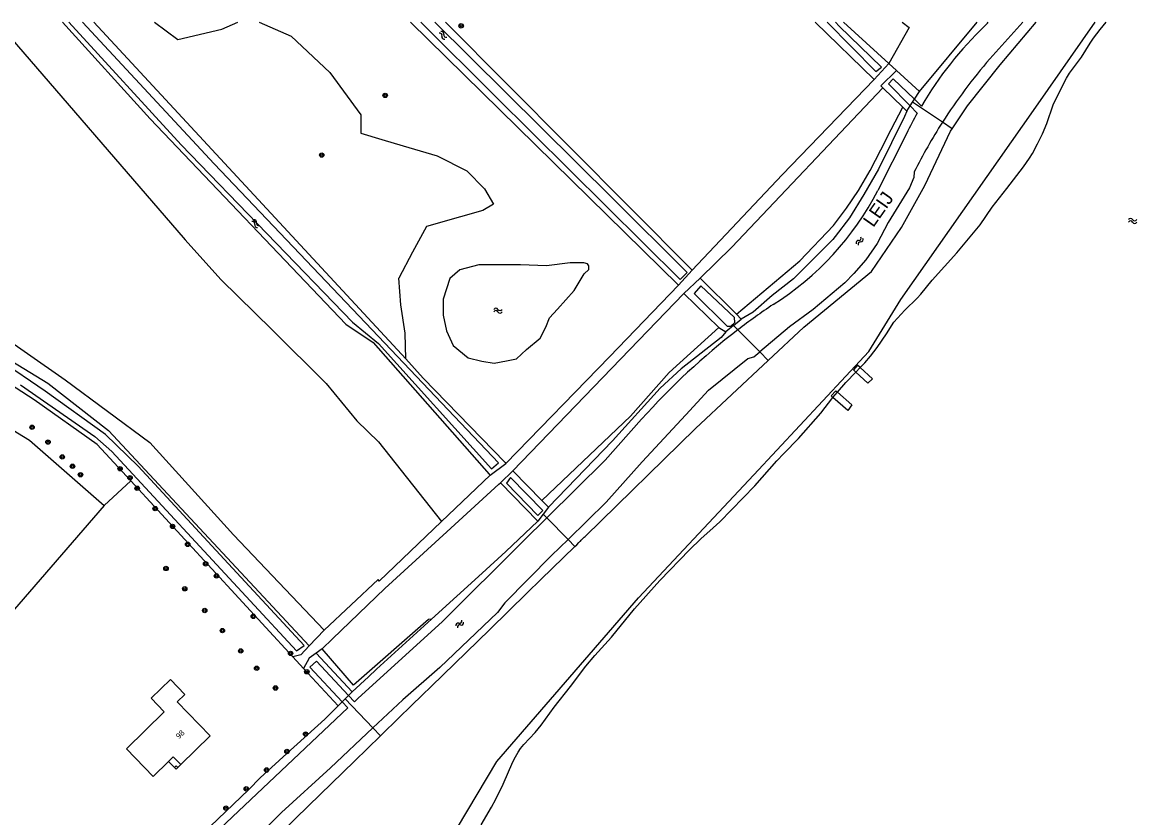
# Model space of a CAD drawing. Extents: x 135990 to 139000, y 393500 to 396000.
# Drawn here: x 136274.9 to 136477.6, y 395855.3 to 396000 of the extents above; entities that cross this region are included whole.
import ezdxf

# ---------------------------------------------------------------- set-up
doc = ezdxf.new("R2010")
doc.units = 0
for name, color, linetype in [('gg-afsc-draadraster', 7, 'Continuous'), ('gg-anno-huisnummerreeks BGT', 7, 'Continuous'), ('gg-anno-naam water', 7, 'Continuous'), ('gg-bbg-hoofdgebouw', 7, 'Continuous'), ('gg-bbg-onder overbouw', 7, 'Continuous'), ('gg-bbg-pand overbouw', 7, 'Continuous'), ('gg-bbg-pilaar onder overbouw', 7, 'Continuous'), ('gg-bbg-pilaar pand', 7, 'Continuous'), ('gg-knt-bronhoudergrens', 7, 'Continuous'), ('gg-kntw-bovenkant insteek waterloop', 7, 'Continuous'), ('gg-kntw-waterlijn', 7, 'Continuous'), ('gg-kwrk-steiger', 7, 'Continuous'), ('gt-grn-groengrens', 7, 'Continuous'), ('gt-grn-vlakafsluiter', 7, 'Continuous'), ('gt-symb-boom', 7, 'Continuous'), ('gt-symb-watersymbool', 7, 'Continuous'), ('gx-grn-maaiveld', 7, 'Continuous')]:
    doc.layers.add(name, color=color, linetype=linetype)

# ---------------------------------------------------------------- blocks, each defined once
blk = doc.blocks.new('gt0-WA')
at = {"layer": 'gt-symb-watersymbool'}
for centre, start, end in [((-0.32, 0.02), 28.0725, 151.9275), ((0.43, 0.42), 208.0725, 331.9275), ((-0.32, -0.43), 28.0725, 151.9275), ((0.43, -0.03), 208.0725, 331.9275)]:
    blk.add_arc(centre, 0.425, start, end, dxfattribs=at)
blk = doc.blocks.new('gt0-BOOM')
at = {"layer": 'gt-symb-boom'}
for radius in [0.4, 0.2]:
    blk.add_circle((0, 0), radius, dxfattribs=at)

msp = doc.modelspace()

# ---------------------------------------------------------------- linework, layer by layer
at = {"layer": 'gg-afsc-draadraster'}
msp.add_lwpolyline([(136404.807, 395946.877), (136414.065, 395954.68), (136416.364, 395956.617), (136422.475, 395963.008), (136424.844, 395966.168), (136427.004, 395969.364), (136429.157, 395973.057), (136431.07, 395976.762), (136432.984, 395980.468), (136435.083, 395984.534)], dxfattribs=at)
at = {"layer": 'gg-bbg-hoofdgebouw'}
msp.add_lwpolyline([(136303.753, 395864.945), (136309.109, 395870.173), (136303.096, 395876.323), (136304.511, 395877.701), (136301.883, 395880.414), (136298.341, 395877.015), (136300.721, 395874.54), (136293.855, 395867.774), (136298.745, 395862.777), (136301.516, 395865.495)], dxfattribs=at)
at = {"layer": 'gg-bbg-onder overbouw'}
msp.add_lwpolyline([(136303.753, 395864.945), (136302.379, 395866.341), (136301.516, 395865.495)], dxfattribs=at)
at = {"layer": 'gg-bbg-pand overbouw'}
for p, q in [((136302.587, 395864.415), (136301.516, 395865.495)), ((136303.197, 395864.407), (136303.753, 395864.945))]:
    msp.add_line(p, q, dxfattribs=at)
at = {"layer": 'gg-bbg-pilaar onder overbouw'}
msp.add_lwpolyline([(136302.587, 395864.415), (136302.892, 395864.714), (136303.197, 395864.407)], dxfattribs=at)
at = {"layer": 'gg-bbg-pilaar pand'}
msp.add_lwpolyline([(136303.197, 395864.407), (136302.892, 395864.108), (136302.587, 395864.415)], dxfattribs=at)
at = {"layer": 'gg-knt-bronhoudergrens'}
msp.add_line((136339.699, 395923.63), (136351.193, 395909.138), dxfattribs=at)
for points in [[(136303.205, 395996.842), (136311.215, 395998.742), (136314.15, 396000)], [(136318.02, 396000), (136323.84, 395997.447), (136330.883, 395990.832), (136336.512, 395983.137), (136336.474, 395979.829), (136340.337, 395978.686), (136344.2, 395977.543), (136350.383, 395975.714), (136355.793, 395972.962), (136358.998, 395969.696), (136360.651, 395966.922), (136358.69, 395965.753), (136354.63, 395964.609), (136348.417, 395962.86), (136345.92, 395958.155), (136343.422, 395953.45)], [(136320.39, 395792.016), (136319.438, 395800.186), (136329.304, 395811.673), (136345.256, 395838.593), (136361.208, 395865.513), (136387.012, 395895.255), (136407.961, 395917.661), (136428.91, 395940.067), (136434.722, 395949.528), (136459.277, 395984.583), (136470.076, 396000)], [(136304.542, 395960.422), (136311.058, 395953.217), (136320.359, 395944.02), (136330.202, 395934.287), (136335.789, 395927.454), (136339.699, 395923.63)]]:
    msp.add_lwpolyline(points, dxfattribs=at)
at = {"layer": 'gg-kntw-bovenkant insteek waterloop'}
for p, q in [((136287.929, 396000), (136344.698, 395938.737)), ((136345.523, 396000), (136394.256, 395952.175)), ((136351.908, 396000), (136396.766, 395954.888)), ((136419.148, 396000), (136429.853, 395989.609)), ((136424.321, 396000), (136432.558, 395992.482)), ((136429.853, 395989.609), (136432.558, 395992.482)), ((136431.071, 395988.427), (136433.928, 395991.231)), ((136433.928, 395991.231), (136438.115, 395987.41)), ((136431.071, 395988.427), (136431.457, 395988.053)), ((136431.457, 395988.053), (136435.083, 395984.534)), ((136435.083, 395984.534), (136435.813, 395983.825)), ((136394.256, 395952.175), (136396.766, 395954.888)), ((136398.199, 395953.46), (136404.807, 395946.877)), ((136404.807, 395946.877), (136405.702, 395945.986)), ((136344.698, 395938.737), (136347.864, 395935.237)), ((136347.864, 395935.237), (136362.748, 395919.867)), ((136426.56, 395936.348), (136427.339, 395937.155)), ((136422.384, 395931.704), (136423.18, 395932.688)), ((136360.026, 395917.574), (136362.903, 395919.707)), ((136362.748, 395919.867), (136362.903, 395919.707)), ((136359.83, 395917.773), (136360.026, 395917.574)), ((136364.167, 395918.402), (136369.421, 395912.977)), ((136324.114, 395884.562), (136294.641, 395916.542)), ((136369.421, 395912.977), (136370.614, 395911.745)), ((136328.356, 395885.218), (136334.916, 395878.188)), ((136332.359, 395875.615), (136326.092, 395882.416)), ((136337.862, 395880.923), (136334.916, 395878.188))]:
    msp.add_line(p, q, dxfattribs=at)
for points in [[(136282.243, 396000), (136298.197, 395982.451), (136333.797, 395945.089), (136338.731, 395941.741), (136359.83, 395917.773)], [(136427.339, 395937.155), (136428.208, 395938.056), (136429.232, 395939.225), (136430.452, 395940.803), (136432.129, 395943.292), (136433.44, 395945.401), (136435.465, 395947.616), (136437.682, 395949.799), (136438.341, 395950.551), (136440.418, 395953.091), (136444.895, 395958.034), (136449.151, 395963.17), (136451.371, 395966.364), (136454.028, 395969.728), (136457.053, 395973.713), (136458.125, 395975.28), (136458.65, 395976.131), (136459.619, 395977.882), (136460.528, 395979.726), (136461.312, 395981.567), (136462.464, 395984.948), (136462.974, 395986.136), (136464.877, 395989.817), (136465.42, 395990.713), (136467.606, 395993.65), (136469.189, 395996.199), (136469.8, 395997.097), (136471.019, 395998.682), (136472.103, 396000)], [(136151.86, 395992.871), (136150.244, 395991.832), (136150.736, 395991.101), (136152.541, 395989.289), (136160.654, 395986.547), (136187.413, 395976.377), (136267.176, 395941.857), (136279.571, 395934.316), (136290.57, 395925.713), (136327.125, 395886.537)], [(136435.813, 395983.825), (136435.373, 395982.85), (136430.668, 395973.259), (136428.006, 395968.686), (136425.39, 395964.42), (136422.81, 395961.042)], [(136422.81, 395961.042), (136422.359, 395960.451), (136415.212, 395953.307), (136411.347, 395950.289), (136407.893, 395947.278), (136405.702, 395945.986)], [(136402.915, 395943.652), (136402.031, 395942.648), (136394.766, 395936.925), (136390.964, 395933.45), (136382.295, 395923.838), (136370.614, 395911.745)], [(136294.641, 395916.542), (136288.506, 395923.2), (136277.06, 395931.3), (136268.239, 395936.998), (136260.701, 395940.796)], [(136423.18, 395932.688), (136424.732, 395934.454), (136426.56, 395936.348)], [(136365.108, 395867.181), (136365.536, 395867.822), (136366.158, 395868.598), (136368.23, 395870.778), (136369.301, 395872.069), (136371.657, 395875.384), (136374.63, 395879.146), (136377.446, 395882.848), (136379.071, 395884.756), (136382.102, 395888.099), (136386.277, 395893.258), (136390.917, 395898.425), (136396.257, 395904.002), (136398.358, 395906.032), (136400.615, 395908.011), (136401.776, 395909.117), (136408.15, 395915.64), (136412.169, 395920.208), (136413.437, 395921.555), (136416.083, 395924.246), (136420.166, 395928.895), (136422.384, 395931.704)], [(136327.125, 395886.537), (136325.558, 395884.915), (136324.114, 395884.562)], [(136328.356, 395885.218), (136327.087, 395884.309), (136326.092, 395882.416)], [(136332.359, 395875.615), (136329.962, 395873.177), (136323.008, 395866.952), (136318.207, 395862.493), (136316.111, 395860.371), (136309.067, 395853.686), (136301.51, 395846.687), (136295.745, 395842.008), (136293.093, 395839.723), (136290.454, 395836.727), (136287.413, 395833.419), (136284.119, 395830.106), (136275.654, 395820.442), (136274.363, 395818.915), (136272.255, 395816.315)], [(136358.365, 395853.941), (136360.27, 395857.184), (136361.079, 395858.643), (136362.4, 395861.338), (136364.177, 395865.406), (136364.617, 395866.31), (136365.108, 395867.181)]]:
    msp.add_lwpolyline(points, dxfattribs=at)
at = {"layer": 'gg-kntw-waterlijn'}
for p, q in [((136437.199, 395985.983), (136433.345, 395989.727)), ((136438.46, 395984.758), (136437.199, 395985.983)), ((136436.418, 395984.767), (136437.712, 395983.46)), ((136435.796, 395979.798), (136430.555, 395969.379)), ((136334.154, 395875.239), (136333.101, 395876.362)), ((136334.249, 395877.517), (136335.337, 395876.357))]:
    msp.add_line(p, q, dxfattribs=at)
for points in [[(136283.399, 396000), (136303.843, 395977.727), (136335.007, 395945.415), (136339.732, 395941.543), (136360.259, 395918.754), (136361.529, 395919.848), (136338.54, 395944.037), (136309.83, 395974.245), (136285.884, 396000)], [(136347.382, 396000), (136360.909, 395986.583), (136394.574, 395953.192), (136395.864, 395954.493), (136382.214, 395968.033), (136349.984, 396000)], [(136421.35, 396000), (136430.206, 395991.047), (136431.196, 395991.815), (136423.502, 395999.29), (136422.842, 396000)], [(136433.345, 395989.727), (136432.456, 395988.773), (136436.418, 395984.767)], [(136360.748, 395937.975), (136363.008, 395938.412), (136364.83, 395938.777), (136366.653, 395940.453), (136369.131, 395942.495), (136370.152, 395944.536), (136370.808, 395946.212), (136372.266, 395947.816), (136375.328, 395951.169), (136377.15, 395954.231), (136377.952, 395955.033), (136377.952, 395955.689), (136377.733, 395956.053), (136377.077, 395956.199), (136374.599, 395956.199), (136370.298, 395955.689), (136365.56, 395955.835), (136361.915, 395955.835), (136357.978, 395955.835), (136354.479, 395954.96), (136352.657, 395953.356), (136351.49, 395949.638), (136351.49, 395946.723), (136352.074, 395943.88), (136353.313, 395941.182), (136356.01, 395938.923), (136358.488, 395938.339), (136360.748, 395937.975)], [(136397.121, 395950.674), (136403.124, 395944.724), (136403.793, 395944.687), (136404.555, 395945.393), (136404.463, 395946.304), (136398.347, 395952.032), (136397.121, 395950.674)], [(136274.582, 395934.054), (136288.114, 395924.649), (136291.199, 395921.877), (136316.39, 395894.729), (136324.814, 395885.651), (136326.176, 395886.614), (136311.631, 395902.333), (136296.015, 395919.211), (136290.03, 395924.994), (136279.098, 395932.901), (136270.859, 395938.459)], [(136362.973, 395916.115), (136368.698, 395910.277), (136369.618, 395911.179), (136363.728, 395917.186), (136362.973, 395916.115)], [(136333.101, 395876.362), (136327.219, 395882.635), (136328.406, 395883.748), (136334.249, 395877.517)], [(136334.154, 395875.239), (136314.263, 395856.43), (136289.01, 395832.551), (136283.009, 395826.197), (136259.042, 395798.523)]]:
    msp.add_lwpolyline(points, dxfattribs=at)
for centre, radius, start, end in [((136497.587, 395949.803), 68.687, 133.78758, 149.40948), ((136358.817, 396087.633), 126.932, 315.95645, 316.3389), ((136497.263, 395949.97), 68.322, 150.64769, 154.11416), ((136382.854, 395994.097), 53.725, 302.22853, 332.60806)]:
    msp.add_arc(centre, radius, start, end, dxfattribs=at)
at = {"layer": 'gg-kwrk-steiger'}
for p, q in [((136426.845, 395937.608), (136426.097, 395936.78)), ((136427.339, 395937.155), (136426.845, 395937.608)), ((136426.097, 395936.78), (136426.56, 395936.348))]:
    msp.add_line(p, q, dxfattribs=at)
for points in [[(136426.56, 395936.348), (136428.734, 395934.32), (136429.584, 395935.098), (136427.339, 395937.155)], [(136422.384, 395931.704), (136422.047, 395931.996), (136422.875, 395932.953), (136423.18, 395932.688)], [(136423.18, 395932.688), (136425.83, 395930.393), (136425.087, 395929.363), (136422.384, 395931.704)]]:
    msp.add_lwpolyline(points, dxfattribs=at)
at = {"layer": 'gt-grn-groengrens'}
for p, q in [((136270.332, 396000), (136304.542, 395960.422)), ((136298.94, 396000), (136303.205, 395996.842)), ((136432.558, 395992.482), (136433.928, 395991.231)), ((136360.026, 395917.574), (136351.193, 395909.138)), ((136289.783, 395912.065), (136294.641, 395916.542)), ((136289.783, 395912.065), (136250.503, 395866.604)), ((136351.193, 395909.138), (136339.861, 395898.315)), ((136339.63, 395898.628), (136329.847, 395889.355)), ((136339.861, 395898.315), (136339.63, 395898.628)), ((136329.847, 395889.355), (136327.125, 395886.537)), ((136329.459, 395886.008), (136331.322, 395887.803)), ((136324.114, 395884.562), (136326.092, 395882.416)), ((136329.459, 395886.008), (136328.356, 395885.218))]:
    msp.add_line(p, q, dxfattribs=at)
for points in [[(136187.706, 396000), (136163.811, 395990.712), (136162.186, 395989.628), (136200.373, 395973.92), (136241.539, 395956.317), (136268.351, 395944.942), (136282.705, 395934.921), (136298.142, 395923.546), (136313.308, 395906.755), (136329.847, 395889.355)], [(136396.766, 395954.888), (136413.136, 395972.267), (136429.853, 395989.609)], [(136431.457, 395988.053), (136403.983, 395959.1), (136398.199, 395953.46)], [(136344.698, 395938.737), (136344.559, 395943.435), (136343.766, 395948.595), (136343.422, 395953.45)], [(136362.903, 395919.707), (136381.744, 395939.109), (136394.256, 395952.175)], [(136234.926, 395944.469), (136259.914, 395933.886), (136276.21, 395923.984), (136289.783, 395912.065)], [(136331.322, 395887.803), (136340.846, 395896.977), (136352.137, 395907.301)]]:
    msp.add_lwpolyline(points, dxfattribs=at)
at = {"layer": 'gt-grn-vlakafsluiter'}
for p, q in [((136437.199, 395985.983), (136438.115, 395987.41)), ((136435.813, 395983.825), (136436.418, 395984.767)), ((136332.359, 395875.615), (136333.101, 395876.362)), ((136334.249, 395877.517), (136334.916, 395878.188))]:
    msp.add_line(p, q, dxfattribs=at)
at = {"layer": 'gx-grn-maaiveld'}
for p, q in [((136438.115, 395987.41), (136448.595, 396000)), ((136450.914, 395993.336), (136456.895, 396000)), ((136436.877, 395985.481), (136437.199, 395985.983)), ((136436.418, 395984.767), (136436.877, 395985.481)), ((136442.299, 395981.811), (136436.877, 395985.481)), ((136444.055, 395980.622), (136442.299, 395981.811)), ((136395.225, 395950.67), (136398.199, 395953.46)), ((136395.225, 395950.67), (136401.632, 395944.468)), ((136404.318, 395944.827), (136405.702, 395945.986)), ((136401.632, 395944.468), (136402.915, 395943.652)), ((136404.318, 395944.827), (136402.915, 395943.652)), ((136405.094, 395944.038), (136404.318, 395944.827)), ((136405.094, 395944.038), (136409.052, 395940.014)), ((136409.052, 395940.014), (136410.6, 395938.44)), ((136361.878, 395916.218), (136364.167, 395918.402)), ((136352.137, 395907.301), (136361.611, 395915.963)), ((136361.611, 395915.963), (136361.878, 395916.218)), ((136368.696, 395909.217), (136361.878, 395916.218)), ((136370.614, 395911.745), (136369.68, 395910.514)), ((136369.68, 395910.514), (136368.696, 395909.217)), ((136369.68, 395910.514), (136370.349, 395909.832)), ((136370.349, 395909.832), (136374.191, 395905.907)), ((136375.446, 395904.625), (136374.191, 395905.907)), ((136358.559, 395899.755), (136349.34, 395891.381)), ((136349.34, 395891.381), (136348.815, 395891.31)), ((136333.101, 395876.362), (136333.624, 395876.888)), ((136333.624, 395876.888), (136334.249, 395877.517)), ((136338.692, 395871.621), (136333.624, 395876.888)), ((136338.692, 395871.621), (136340.079, 395870.179))]:
    msp.add_line(p, q, dxfattribs=at)
for points in [[(136434.973, 396000), (136436.23, 395999.046), (136432.558, 395992.482)], [(136444.055, 395980.622), (136446.845, 395984.814), (136452.773, 395992.272), (136459.362, 396000)], [(136410.6, 395938.44), (136417.106, 395944.544), (136429.411, 395954.669), (136434.865, 395962.664), (136439.072, 395970.287), (136443.768, 395980.191), (136444.055, 395980.622)], [(136437.181, 395972.761), (136437.064, 395971.764), (136436.289, 395969.862), (136432.449, 395963.539), (136430.45, 395959.728), (136428.347, 395956.796), (136426.151, 395954.294), (136424.569, 395952.615), (136418.802, 395947.717), (136414.489, 395944.578), (136409.052, 395940.014)], [(136364.167, 395918.402), (136395.21, 395950.609), (136395.225, 395950.67)], [(136369.421, 395912.977), (136385.57, 395928.354), (136392.581, 395936.292), (136401.632, 395944.468)], [(136374.191, 395905.907), (136381.11, 395912.661), (136387.691, 395920.004), (136395.6, 395928.543), (136399.754, 395933.028), (136406.878, 395938.818), (136408.016, 395939.144), (136409.052, 395940.014)], [(136375.446, 395904.625), (136375.767, 395904.937), (136376.153, 395905.312), (136376.335, 395905.49), (136376.455, 395905.607), (136376.591, 395905.739), (136377.146, 395906.28), (136377.29, 395906.42), (136397.4, 395926.055), (136410.6, 395938.44)], [(136370.349, 395909.832), (136380.918, 395920.326), (136387.566, 395927.756)], [(136370.349, 395909.832), (136366.109, 395905.622), (136351.3, 395890.918), (136336.018, 395877.001), (136335.337, 395876.357)], [(136368.696, 395909.217), (136362.887, 395903.687), (136358.559, 395899.755)], [(136374.191, 395905.907), (136371.168, 395902.957), (136362.701, 395894.368), (136361.363, 395892.583), (136350.874, 395882.604), (136344.121, 395876.729), (136338.692, 395871.621)], [(136340.079, 395870.179), (136340.26, 395870.355), (136343.363, 395873.377), (136345.7, 395875.654), (136347.674, 395877.577), (136349.282, 395879.142), (136359.94, 395889.522), (136366.773, 395896.177), (136369.253, 395898.593), (136375.446, 395904.625)], [(136348.815, 395891.31), (136335.148, 395879.394), (136329.459, 395886.008)], [(136349.34, 395891.381), (136339.365, 395882.318), (136337.862, 395880.923)], [(136259.078, 395790.707), (136263.121, 395794.803), (136271.516, 395803.601), (136287.215, 395821.374), (136304.092, 395838.448), (136322.089, 395856.212), (136330.973, 395864.357), (136338.692, 395871.621)], [(136259.773, 395789.823), (136260.953, 395790.755), (136265.427, 395795.677), (136275.005, 395805.691), (136287.406, 395818.658), (136290.495, 395821.887), (136302.319, 395833.404), (136309.95, 395840.835), (136319.24, 395849.883), (136322.115, 395852.683), (136326.958, 395857.4), (136335.346, 395865.57), (136340.079, 395870.179)]]:
    msp.add_lwpolyline(points, dxfattribs=at)
for centre, radius, start, end in [((136524.649, 395929.236), 97.702, 138.99876, 147.44461), ((136524.418, 395929.398), 97.42, 147.45192, 153.5696), ((136483.004, 395842.477), 128.003, 123.95724, 127.4926), ((136482.596, 395843.03), 127.316, 127.49834, 138.28053)]:
    msp.add_arc(centre, radius, start, end, dxfattribs=at)

# ---------------------------------------------------------------- block references
at = {"layer": 'gt-symb-boom'}
for p in [(136354.744, 395999.348), (136340.927, 395986.701), (136329.391, 395975.839), (136276.698, 395926.301), (136279.593, 395923.606), (136282.185, 395920.91), (136284.047, 395919.215), (136292.697, 395918.762), (136285.498, 395917.665), (136294.507, 395917.116), (136295.813, 395915.209), (136299.082, 395911.506), (136302.244, 395908.259), (136304.998, 395905.005), (136301.053, 395900.613), (136308.268, 395901.455), (136310.241, 395899.254), (136304.474, 395896.913), (136308.104, 395892.963), (136316.933, 395891.903), (136311.322, 395889.31), (136314.646, 395885.609), (136323.713, 395885.163), (136317.552, 395882.459), (136326.67, 395881.81), (136320.973, 395878.861), (136326.457, 395870.471), (136323.061, 395867.307), (136319.36, 395863.937), (136315.663, 395860.516), (136311.963, 395856.992)]:
    msp.add_blockref('gt0-BOOM', p, dxfattribs=at)
at = {"layer": 'gt-symb-watersymbool'}
for p, rotation in [((136351.384, 395997.68), -44.51376743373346), ((136317.319, 395963.421), -45.48623256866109), ((136427.198, 395960.137), 55.547516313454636), ((136361.498, 395947.523), 180), ((136354.435, 395890.462), 43.379618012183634)]:
    msp.add_blockref('gt0-WA', p, dxfattribs=dict(at, rotation=rotation))
msp.add_blockref('gt0-WA', (136476.835, 395963.87), dxfattribs=at)

# ---------------------------------------------------------------- texts
at = {"layer": 'gg-anno-huisnummerreeks BGT'}
msp.add_text('98', height=1, rotation=44.3, dxfattribs=at).set_placement((136303.43, 395869.52))
at = {"layer": 'gg-anno-naam water'}
msp.add_text('LEIJ', height=2.5, rotation=54.89531, dxfattribs=at).set_placement((136429.718, 395962.549))

doc.saveas('drawing.dxf')
